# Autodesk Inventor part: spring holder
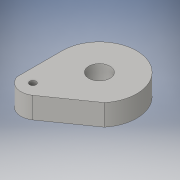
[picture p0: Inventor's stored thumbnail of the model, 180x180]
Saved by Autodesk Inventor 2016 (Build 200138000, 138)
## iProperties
Created: 2020-02
Part Number: spring holder
Material: Generic
Document SubType Name: Modeling
Designer: merlin
Density: 1 g/cm^3
Appearance: Default
Author: merlin
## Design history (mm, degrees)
sketch "Sketch1"
  geometry: L1 (22.225, 0)-(22.225, 26.988); L2 (-17.074, 14.228)-(7.938, 31.75); C1 r 6.35 at (0, 0); A1 r 22.225 centre (0, 0) between (-17.074, 14.228) and (22.225, 0); A2 r 9.374 centre (13.316, 24.073) between (22.225, 26.988) and (7.938, 31.75); 1 further point
  constraints: 4 end point, 4 point on circle, 3 centre point, 2 coincident, 1 tangent, 1 vertical
  dimensions: "d0" = 12.7 diameter of C1
extrude "Extrusion1" new body sketch "Sketch1" distance "d1" = 12.7; taper "d2" = 0 deg
sketch "Sketch2"
  geometry: C1 r 1.587 at (-14.287, -25.4); 1 further point
  constraints: 1 centre point
hole "Hole1" sketch "Sketch2" at (-14.287, -25.4) diameter "d3" = 3.81; stored, may be unused: countersink angle "d7" = 82 deg, drill point angle "d9" = 118 deg; dims "d4" = 19.05, "d5" = 9.525, "d6" = 6.35, "d8" = 25.4
body "Solid1"
